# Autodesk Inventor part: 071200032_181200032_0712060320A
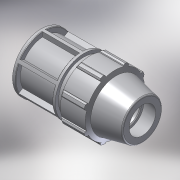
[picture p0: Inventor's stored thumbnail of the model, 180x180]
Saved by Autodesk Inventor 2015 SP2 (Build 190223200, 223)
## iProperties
Created: 2017-02
Part Number: 071200032_181200032_0712060320A
Material: PVC-Piping
Description: PLASSON END PLUG 32
Document SubType Name: Modeling
Designer: KIM
Mass: 92.6774 g
Surface Area: 199.44 cm^2
Volume: 66.1981 cm^3
Density: 1.4 g/cm^3
Appearance: Smooth - White
Author: Кирилл
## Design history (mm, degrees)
derived "07120.ipt"
feature "Solid1::07120.ipt"
tag "TaggingFeature1"
body "Solid1"
other parameters: "d2" = 32, "d4" = 13.14286, "d5" = 23, "d7" = 64, "d8" = 48, "d9" = 13.14286, "d11" = 2.62857, "d12" = 51.2, "d13" = 120 deg, "d14" = 48, "d15" = 12 deg, "d16" = 57.6, "d18" = 1.6, "d19" = 35 deg, "d20" = 17.5 deg, "d21" = 59.52, "d23" = 0, "d25" = 360 deg, "d27" = 1.28, "d34" = 3.2, "d36" = 0, "d42" = 23, "d43" = 1.92, "d46" = 0.96, "d53" = 0.64, "d55" = 360 deg, "d59" = 32.2, "d64" = 92, "d66" = 6.4, "d67" = 3.2, "d68" = 87, "d_" = 32, "E_" = 64, "H_" = 92, "l_" = 87
